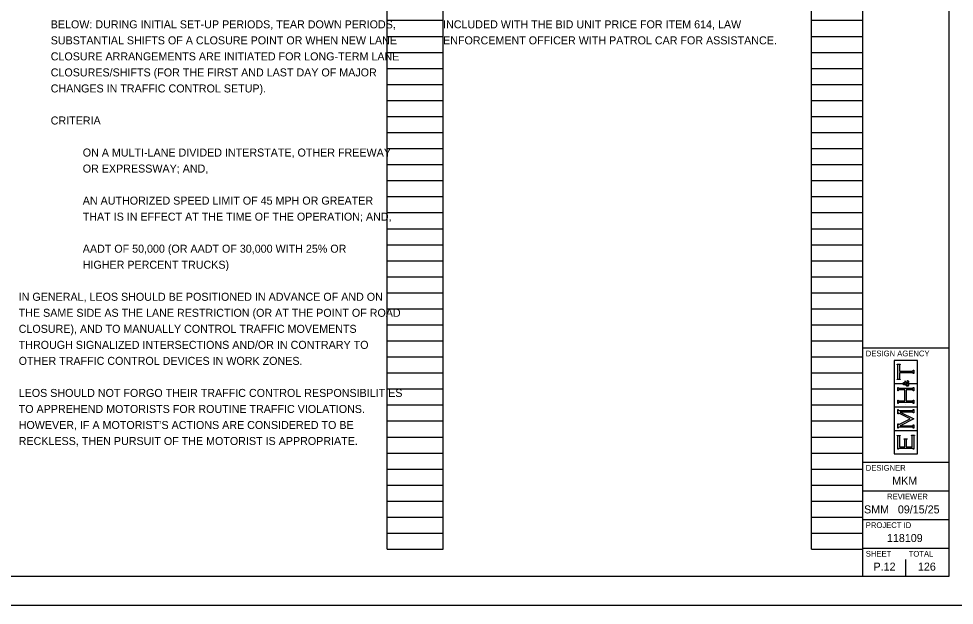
# Model space of a CAD drawing. Extents: x 0 to 50.5, y 0 to 22.
# Drawn here: x 17.24 to 33.6, y 0 to 10.25 of the extents above; entities that cross this region are included whole.
import ezdxf

# ---------------------------------------------------------------- set-up
doc = ezdxf.new("R2010")
doc.units = 0
for name, color, linetype in [('SH_Border', 7, 'Continuous'), ('SH_Cut_Line', 7, 'Continuous'), ('SH_Data', 7, 'Continuous'), ('SH_Text', 7, 'Continuous')]:
    doc.layers.add(name, color=color, linetype=linetype)

msp = doc.modelspace()

# ---------------------------------------------------------------- linework, layer by layer
at = {"layer": 'SH_Border'}
for p, q in [((32, 0.5), (32, 21.5)), ((32, 4.5), (33.5, 4.5)), ((32, 2.5), (33.5, 2.5)), ((32, 2), (33.5, 2)), ((32, 1.5), (33.5, 1.5)), ((32, 1), (33.5, 1))]:
    msp.add_line(p, q, dxfattribs=at)
msp.add_lwpolyline([(1.5, 21.5), (33.5, 21.5), (33.5, 0.5), (1.5, 0.5)], close=True, dxfattribs=at)
at = {"layer": 'SH_Cut_Line'}
msp.add_lwpolyline([(0, 0), (34, 0), (34, 22), (0, 22)], close=True, dxfattribs=at)
at = {"layer": 'SH_Data'}
for p, q in [((23.68, 0.98), (23.68, 21.14)), ((24.66, 0.98), (24.66, 21.14)), ((31.1, 0.98), (31.1, 21.14)), ((32, 0.98), (32, 21.14)), ((23.68, 10.22), (24.66, 10.22)), ((31.1, 10.22), (32, 10.22)), ((23.68, 9.94), (24.66, 9.94)), ((31.1, 9.94), (32, 9.94)), ((23.68, 9.66), (24.66, 9.66)), ((31.1, 9.66), (32, 9.66)), ((23.68, 9.38), (24.66, 9.38)), ((31.1, 9.38), (32, 9.38)), ((23.68, 9.1), (24.66, 9.1)), ((31.1, 9.1), (32, 9.1)), ((23.68, 8.82), (24.66, 8.82)), ((31.1, 8.82), (32, 8.82)), ((23.68, 8.54), (24.66, 8.54)), ((31.1, 8.54), (32, 8.54)), ((23.68, 8.26), (24.66, 8.26)), ((31.1, 8.26), (32, 8.26)), ((23.68, 7.98), (24.66, 7.98)), ((31.1, 7.98), (32, 7.98)), ((23.68, 7.7), (24.66, 7.7)), ((31.1, 7.7), (32, 7.7)), ((23.68, 7.42), (24.66, 7.42)), ((31.1, 7.42), (32, 7.42)), ((23.68, 7.14), (24.66, 7.14)), ((31.1, 7.14), (32, 7.14)), ((23.68, 6.86), (24.66, 6.86)), ((31.1, 6.86), (32, 6.86)), ((23.68, 6.58), (24.66, 6.58)), ((31.1, 6.58), (32, 6.58)), ((23.68, 6.3), (24.66, 6.3)), ((31.1, 6.3), (32, 6.3)), ((23.68, 6.02), (24.66, 6.02)), ((31.1, 6.02), (32, 6.02)), ((23.68, 5.74), (24.66, 5.74)), ((31.1, 5.74), (32, 5.74)), ((23.68, 5.46), (24.66, 5.46)), ((31.1, 5.46), (32, 5.46)), ((23.68, 5.18), (24.66, 5.18)), ((31.1, 5.18), (32, 5.18)), ((23.68, 4.9), (24.66, 4.9)), ((31.1, 4.9), (32, 4.9)), ((23.68, 4.62), (24.66, 4.62)), ((31.1, 4.62), (32, 4.62)), ((23.68, 4.34), (24.66, 4.34)), ((31.1, 4.34), (32, 4.34)), ((32.952, 4.279), (32.547, 4.279)), ((32.547, 4.279), (32.547, 3.875)), ((32.952, 3.875), (32.952, 4.279)), ((32.598, 4.204), (32.598, 4.211)), ((32.598, 4.211), (32.65, 4.211)), ((32.603, 4.203), (32.598, 4.204)), ((32.606, 4.201), (32.603, 4.203)), ((32.608, 4.199), (32.606, 4.201)), ((32.61, 4.196), (32.608, 4.199)), ((32.611, 4.192), (32.61, 4.196)), ((32.611, 4.187), (32.611, 4.192)), ((32.611, 3.968), (32.611, 4.187)), ((32.638, 4.196), (32.637, 4.192)), ((32.637, 4.192), (32.637, 4.187)), ((32.637, 4.187), (32.637, 4.093)), ((32.637, 4.093), (32.864, 4.093)), ((32.64, 4.199), (32.638, 4.196)), ((32.642, 4.201), (32.64, 4.199)), ((32.645, 4.203), (32.642, 4.201)), ((32.65, 4.204), (32.645, 4.203)), ((32.65, 4.211), (32.65, 4.204)), ((32.864, 4.093), (32.869, 4.093)), ((32.869, 4.093), (32.873, 4.094)), ((32.873, 4.094), (32.876, 4.096)), ((32.876, 4.096), (32.878, 4.097)), ((32.878, 4.097), (32.88, 4.101)), ((32.88, 4.101), (32.881, 4.106)), ((32.881, 4.106), (32.888, 4.106)), ((32.888, 4.106), (32.888, 4.048)), ((23.68, 4.06), (24.66, 4.06)), ((31.1, 4.06), (32, 4.06)), ((32.598, 3.95), (32.603, 3.951)), ((32.598, 3.944), (32.598, 3.95)), ((32.65, 3.944), (32.598, 3.944)), ((32.603, 3.951), (32.606, 3.953)), ((32.606, 3.953), (32.608, 3.955)), ((32.608, 3.955), (32.61, 3.958)), ((32.61, 3.958), (32.611, 3.962)), ((32.611, 3.962), (32.611, 3.968)), ((32.864, 4.061), (32.637, 4.061)), ((32.637, 4.061), (32.637, 3.968)), ((32.637, 3.968), (32.637, 3.962)), ((32.637, 3.962), (32.638, 3.958)), ((32.638, 3.958), (32.64, 3.955)), ((32.64, 3.955), (32.642, 3.953)), ((32.642, 3.953), (32.645, 3.951)), ((32.645, 3.951), (32.65, 3.95)), ((32.65, 3.95), (32.65, 3.944)), ((32.779, 3.923), (32.781, 3.926)), ((32.781, 3.926), (32.787, 3.924)), ((32.87, 4.061), (32.864, 4.061)), ((32.874, 4.06), (32.87, 4.061)), ((32.876, 4.059), (32.874, 4.06)), ((32.878, 4.057), (32.876, 4.059)), ((32.88, 4.053), (32.878, 4.057)), ((32.881, 4.048), (32.88, 4.053)), ((32.888, 4.048), (32.881, 4.048)), ((23.68, 3.78), (24.66, 3.78)), ((31.1, 3.78), (32, 3.78)), ((32.547, 3.875), (32.696, 3.875)), ((32.696, 3.869), (32.547, 3.869)), ((32.547, 3.869), (32.547, 3.465)), ((32.611, 3.749), (32.611, 3.807)), ((32.611, 3.807), (32.617, 3.807)), ((32.617, 3.807), (32.619, 3.802)), ((32.619, 3.802), (32.62, 3.798)), ((32.62, 3.798), (32.623, 3.797)), ((32.623, 3.797), (32.625, 3.795)), ((32.625, 3.795), (32.629, 3.794)), ((32.629, 3.762), (32.625, 3.761)), ((32.629, 3.794), (32.635, 3.794)), ((32.635, 3.762), (32.629, 3.762)), ((32.635, 3.794), (32.864, 3.794)), ((32.732, 3.762), (32.635, 3.762)), ((32.696, 3.875), (32.696, 3.869)), ((32.703, 3.879), (32.705, 3.883)), ((32.703, 3.873), (32.703, 3.879)), ((32.703, 3.868), (32.703, 3.873)), ((32.705, 3.863), (32.703, 3.868)), ((32.705, 3.883), (32.708, 3.887)), ((32.708, 3.858), (32.705, 3.863)), ((32.708, 3.887), (32.711, 3.89)), ((32.709, 3.879), (32.708, 3.876)), ((32.708, 3.876), (32.708, 3.873)), ((32.708, 3.873), (32.708, 3.869)), ((32.708, 3.869), (32.71, 3.866)), ((32.712, 3.853), (32.708, 3.858)), ((32.712, 3.881), (32.709, 3.879)), ((32.71, 3.866), (32.712, 3.864)), ((32.711, 3.89), (32.715, 3.892)), ((32.714, 3.883), (32.712, 3.881)), ((32.712, 3.864), (32.715, 3.862)), ((32.718, 3.85), (32.712, 3.853)), ((32.716, 3.884), (32.714, 3.883)), ((32.715, 3.892), (32.72, 3.892)), ((32.715, 3.862), (32.718, 3.861)), ((32.72, 3.884), (32.716, 3.884)), ((32.718, 3.861), (32.721, 3.861)), ((32.726, 3.85), (32.718, 3.85)), ((32.72, 3.892), (32.725, 3.892)), ((32.724, 3.884), (32.72, 3.884)), ((32.721, 3.861), (32.723, 3.861)), ((32.723, 3.861), (32.725, 3.862)), ((32.728, 3.882), (32.724, 3.884)), ((32.725, 3.892), (32.729, 3.89)), ((32.725, 3.862), (32.728, 3.862)), ((32.729, 3.85), (32.726, 3.85)), ((32.731, 3.88), (32.728, 3.882)), ((32.728, 3.862), (32.731, 3.863)), ((32.729, 3.89), (32.732, 3.887)), ((32.731, 3.85), (32.729, 3.85)), ((32.734, 3.877), (32.731, 3.88)), ((32.731, 3.863), (32.735, 3.865)), ((32.734, 3.851), (32.731, 3.85)), ((32.732, 3.887), (32.736, 3.883)), ((32.732, 3.572), (32.732, 3.762)), ((32.737, 3.872), (32.734, 3.877)), ((32.737, 3.852), (32.734, 3.851)), ((32.735, 3.865), (32.74, 3.867)), ((32.736, 3.883), (32.74, 3.878)), ((32.74, 3.867), (32.737, 3.872)), ((32.741, 3.853), (32.737, 3.852)), ((32.738, 3.893), (32.738, 3.922)), ((32.738, 3.922), (32.741, 3.922)), ((32.741, 3.893), (32.738, 3.893)), ((32.74, 3.878), (32.744, 3.869)), ((32.741, 3.922), (32.741, 3.918)), ((32.741, 3.918), (32.742, 3.915)), ((32.742, 3.896), (32.741, 3.895)), ((32.741, 3.895), (32.741, 3.893)), ((32.746, 3.855), (32.741, 3.853)), ((32.742, 3.915), (32.743, 3.913)), ((32.743, 3.897), (32.742, 3.896)), ((32.743, 3.913), (32.745, 3.911)), ((32.745, 3.899), (32.743, 3.897)), ((32.744, 3.869), (32.754, 3.875)), ((32.745, 3.911), (32.749, 3.908)), ((32.746, 3.899), (32.745, 3.899)), ((32.748, 3.899), (32.746, 3.899)), ((32.752, 3.844), (32.746, 3.855)), ((32.755, 3.899), (32.748, 3.899)), ((32.749, 3.908), (32.756, 3.904)), ((32.756, 3.86), (32.751, 3.857)), ((32.751, 3.857), (32.754, 3.852)), ((32.757, 3.837), (32.752, 3.844)), ((32.754, 3.875), (32.764, 3.881)), ((32.754, 3.852), (32.757, 3.848)), ((32.763, 3.895), (32.755, 3.899)), ((32.756, 3.904), (32.763, 3.9)), ((32.761, 3.863), (32.756, 3.86)), ((32.757, 3.848), (32.761, 3.845)), ((32.763, 3.833), (32.757, 3.837)), ((32.864, 3.762), (32.759, 3.762)), ((32.759, 3.762), (32.759, 3.572)), ((32.764, 3.865), (32.761, 3.863)), ((32.761, 3.845), (32.765, 3.843)), ((32.763, 3.9), (32.77, 3.896)), ((32.772, 3.887), (32.763, 3.895)), ((32.768, 3.829), (32.763, 3.833)), ((32.764, 3.881), (32.772, 3.887)), ((32.768, 3.867), (32.764, 3.865)), ((32.765, 3.843), (32.769, 3.841)), ((32.774, 3.872), (32.768, 3.867)), ((32.774, 3.827), (32.768, 3.829)), ((32.769, 3.841), (32.773, 3.841)), ((32.77, 3.896), (32.776, 3.891)), ((32.773, 3.841), (32.778, 3.841)), ((32.782, 3.878), (32.774, 3.872)), ((32.779, 3.827), (32.774, 3.827)), ((32.776, 3.891), (32.781, 3.895)), ((32.778, 3.841), (32.782, 3.843)), ((32.782, 3.922), (32.779, 3.923)), ((32.785, 3.827), (32.779, 3.827)), ((32.781, 3.895), (32.784, 3.898)), ((32.785, 3.921), (32.782, 3.922)), ((32.786, 3.873), (32.782, 3.878)), ((32.782, 3.843), (32.786, 3.846)), ((32.784, 3.898), (32.786, 3.901)), ((32.786, 3.919), (32.785, 3.921)), ((32.79, 3.829), (32.785, 3.827)), ((32.788, 3.917), (32.786, 3.919)), ((32.786, 3.901), (32.788, 3.904)), ((32.791, 3.886), (32.786, 3.881)), ((32.786, 3.881), (32.791, 3.876)), ((32.788, 3.869), (32.786, 3.873)), ((32.786, 3.846), (32.789, 3.849)), ((32.787, 3.924), (32.792, 3.921)), ((32.789, 3.914), (32.788, 3.917)), ((32.788, 3.904), (32.789, 3.908)), ((32.79, 3.867), (32.788, 3.869)), ((32.789, 3.911), (32.789, 3.914)), ((32.789, 3.908), (32.789, 3.911)), ((32.789, 3.849), (32.791, 3.853)), ((32.791, 3.864), (32.79, 3.867)), ((32.793, 3.834), (32.79, 3.829)), ((32.794, 3.89), (32.791, 3.886)), ((32.791, 3.876), (32.795, 3.87)), ((32.791, 3.861), (32.791, 3.864)), ((32.791, 3.859), (32.791, 3.861)), ((32.791, 3.853), (32.791, 3.859)), ((32.792, 3.921), (32.795, 3.918)), ((32.797, 3.838), (32.793, 3.834)), ((32.796, 3.894), (32.794, 3.89)), ((32.795, 3.918), (32.798, 3.914)), ((32.795, 3.87), (32.797, 3.866)), ((32.798, 3.897), (32.796, 3.894)), ((32.797, 3.866), (32.798, 3.861)), ((32.799, 3.844), (32.797, 3.838)), ((32.798, 3.914), (32.799, 3.91)), ((32.799, 3.901), (32.798, 3.897)), ((32.798, 3.861), (32.799, 3.857)), ((32.799, 3.91), (32.799, 3.905)), ((32.799, 3.905), (32.799, 3.901)), ((32.803, 3.869), (32.799, 3.875)), ((32.799, 3.875), (32.952, 3.875)), ((32.799, 3.857), (32.799, 3.852)), ((32.799, 3.852), (32.799, 3.844)), ((32.952, 3.869), (32.803, 3.869)), ((32.864, 3.794), (32.869, 3.794)), ((32.87, 3.762), (32.864, 3.762)), ((32.869, 3.794), (32.873, 3.795)), ((32.874, 3.761), (32.87, 3.762)), ((32.873, 3.795), (32.876, 3.797)), ((32.876, 3.797), (32.878, 3.798)), ((32.878, 3.798), (32.88, 3.802)), ((32.88, 3.802), (32.881, 3.807)), ((32.881, 3.807), (32.888, 3.807)), ((32.888, 3.807), (32.888, 3.749)), ((32.952, 3.465), (32.952, 3.869)), ((32.617, 3.749), (32.611, 3.749)), ((32.618, 3.754), (32.617, 3.749)), ((32.62, 3.758), (32.618, 3.754)), ((32.623, 3.76), (32.62, 3.758)), ((32.625, 3.761), (32.623, 3.76)), ((32.876, 3.76), (32.874, 3.761)), ((32.878, 3.758), (32.876, 3.76)), ((32.88, 3.754), (32.878, 3.758)), ((32.881, 3.749), (32.88, 3.754)), ((32.888, 3.749), (32.881, 3.749)), ((23.68, 3.5), (24.66, 3.5)), ((31.1, 3.5), (32, 3.5)), ((32.547, 3.465), (32.952, 3.465)), ((32.952, 3.459), (32.547, 3.459)), ((32.547, 3.459), (32.547, 3.055)), ((32.611, 3.527), (32.611, 3.585)), ((32.611, 3.585), (32.617, 3.585)), ((32.617, 3.527), (32.611, 3.527)), ((32.617, 3.585), (32.619, 3.58)), ((32.618, 3.532), (32.617, 3.527)), ((32.62, 3.536), (32.618, 3.532)), ((32.619, 3.58), (32.62, 3.576)), ((32.62, 3.576), (32.623, 3.574)), ((32.623, 3.537), (32.62, 3.536)), ((32.623, 3.574), (32.625, 3.573)), ((32.625, 3.539), (32.623, 3.537)), ((32.625, 3.573), (32.629, 3.572)), ((32.629, 3.54), (32.625, 3.539)), ((32.629, 3.572), (32.635, 3.572)), ((32.635, 3.54), (32.629, 3.54)), ((32.635, 3.572), (32.732, 3.572)), ((32.864, 3.54), (32.635, 3.54)), ((32.75, 3.5), (32.75, 3.5)), ((32.759, 3.572), (32.864, 3.572)), ((32.864, 3.572), (32.87, 3.572)), ((32.87, 3.54), (32.864, 3.54)), ((32.87, 3.572), (32.874, 3.573)), ((32.874, 3.539), (32.87, 3.54)), ((32.874, 3.573), (32.876, 3.574)), ((32.876, 3.538), (32.874, 3.539)), ((32.876, 3.574), (32.878, 3.576)), ((32.878, 3.536), (32.876, 3.538)), ((32.878, 3.576), (32.88, 3.58)), ((32.88, 3.532), (32.878, 3.536)), ((32.88, 3.58), (32.881, 3.585)), ((32.881, 3.527), (32.88, 3.532)), ((32.881, 3.585), (32.888, 3.585)), ((32.888, 3.527), (32.881, 3.527)), ((32.888, 3.585), (32.888, 3.527)), ((32.952, 3.055), (32.952, 3.459)), ((32.611, 3.345), (32.611, 3.418)), ((32.611, 3.418), (32.617, 3.418)), ((32.617, 3.345), (32.611, 3.345)), ((32.617, 3.418), (32.619, 3.412)), ((32.62, 3.352), (32.617, 3.345)), ((32.619, 3.412), (32.62, 3.409)), ((32.62, 3.409), (32.623, 3.407)), ((32.622, 3.355), (32.62, 3.352)), ((32.626, 3.355), (32.622, 3.355)), ((32.623, 3.407), (32.625, 3.405)), ((32.625, 3.405), (32.629, 3.405)), ((32.629, 3.355), (32.626, 3.355)), ((32.629, 3.405), (32.635, 3.405)), ((32.633, 3.353), (32.629, 3.355)), ((32.64, 3.35), (32.633, 3.353)), ((32.635, 3.405), (32.864, 3.405)), ((32.825, 3.257), (32.64, 3.35)), ((32.864, 3.373), (32.654, 3.373)), ((32.654, 3.373), (32.888, 3.255)), ((32.864, 3.405), (32.869, 3.405)), ((32.87, 3.373), (32.864, 3.373)), ((32.869, 3.405), (32.873, 3.405)), ((32.874, 3.372), (32.87, 3.373)), ((32.873, 3.405), (32.876, 3.407)), ((32.876, 3.37), (32.874, 3.372)), ((32.876, 3.407), (32.878, 3.409)), ((32.878, 3.369), (32.876, 3.37)), ((32.878, 3.409), (32.88, 3.412)), ((32.88, 3.365), (32.878, 3.369)), ((32.88, 3.412), (32.881, 3.418)), ((32.881, 3.36), (32.88, 3.365)), ((32.881, 3.418), (32.888, 3.418)), ((32.888, 3.36), (32.881, 3.36)), ((32.888, 3.418), (32.888, 3.36)), ((23.68, 3.22), (24.66, 3.22)), ((31.1, 3.22), (32, 3.22)), ((32.611, 3.096), (32.611, 3.168)), ((32.611, 3.168), (32.617, 3.168)), ((32.617, 3.168), (32.62, 3.162)), ((32.62, 3.162), (32.622, 3.158)), ((32.622, 3.158), (32.626, 3.158)), ((32.625, 3.109), (32.623, 3.107)), ((32.629, 3.109), (32.625, 3.109)), ((32.626, 3.158), (32.627, 3.158)), ((32.627, 3.158), (32.633, 3.161)), ((32.635, 3.109), (32.629, 3.109)), ((32.633, 3.161), (32.641, 3.165)), ((32.864, 3.109), (32.635, 3.109)), ((32.641, 3.165), (32.825, 3.257)), ((32.888, 3.255), (32.654, 3.138)), ((32.654, 3.138), (32.864, 3.138)), ((32.864, 3.138), (32.869, 3.138)), ((32.87, 3.109), (32.864, 3.109)), ((32.869, 3.138), (32.873, 3.139)), ((32.874, 3.109), (32.87, 3.109)), ((32.873, 3.139), (32.876, 3.141)), ((32.876, 3.107), (32.874, 3.109)), ((32.876, 3.141), (32.878, 3.143)), ((32.878, 3.143), (32.88, 3.146)), ((32.88, 3.146), (32.881, 3.151)), ((32.881, 3.151), (32.888, 3.151)), ((32.888, 3.151), (32.888, 3.096)), ((32.547, 3.055), (32.952, 3.055)), ((32.952, 3.049), (32.547, 3.049)), ((32.547, 3.049), (32.547, 2.645)), ((32.598, 2.962), (32.598, 2.969)), ((32.598, 2.969), (32.65, 2.969)), ((32.603, 2.961), (32.598, 2.962)), ((32.606, 2.959), (32.603, 2.961)), ((32.608, 2.957), (32.606, 2.959)), ((32.61, 2.955), (32.608, 2.957)), ((32.611, 2.951), (32.61, 2.955)), ((32.617, 3.096), (32.611, 3.096)), ((32.611, 2.945), (32.611, 2.951)), ((32.611, 2.725), (32.611, 2.945)), ((32.618, 3.102), (32.617, 3.096)), ((32.62, 3.105), (32.618, 3.102)), ((32.623, 3.107), (32.62, 3.105)), ((32.64, 2.957), (32.638, 2.955)), ((32.638, 2.955), (32.638, 2.951)), ((32.638, 2.951), (32.638, 2.945)), ((32.638, 2.945), (32.638, 2.77)), ((32.642, 2.959), (32.64, 2.957)), ((32.645, 2.961), (32.642, 2.959)), ((32.65, 2.962), (32.645, 2.961)), ((32.65, 2.969), (32.65, 2.962)), ((32.848, 2.965), (32.848, 2.972)), ((32.848, 2.972), (32.901, 2.972)), ((32.853, 2.964), (32.848, 2.965)), ((32.857, 2.962), (32.853, 2.964)), ((32.859, 2.96), (32.857, 2.962)), ((32.86, 2.958), (32.859, 2.96)), ((32.861, 2.953), (32.86, 2.958)), ((32.861, 2.948), (32.861, 2.953)), ((32.861, 2.77), (32.861, 2.948)), ((32.878, 3.105), (32.876, 3.107)), ((32.88, 3.102), (32.878, 3.105)), ((32.881, 3.096), (32.88, 3.102)), ((32.888, 3.096), (32.881, 3.096)), ((32.889, 2.957), (32.888, 2.953)), ((32.888, 2.953), (32.888, 2.948)), ((32.888, 2.948), (32.888, 2.725)), ((32.891, 2.96), (32.889, 2.957)), ((32.892, 2.962), (32.891, 2.96)), ((32.896, 2.964), (32.892, 2.962)), ((32.901, 2.965), (32.896, 2.964)), ((32.901, 2.972), (32.901, 2.965)), ((32.952, 2.645), (32.952, 3.049)), ((23.68, 2.94), (24.66, 2.94)), ((31.1, 2.94), (32, 2.94)), ((32.719, 2.902), (32.719, 2.908)), ((32.719, 2.908), (32.772, 2.908)), ((32.724, 2.901), (32.719, 2.902)), ((32.728, 2.899), (32.724, 2.901)), ((32.729, 2.896), (32.728, 2.899)), ((32.731, 2.894), (32.729, 2.896)), ((32.732, 2.89), (32.731, 2.894)), ((32.732, 2.884), (32.732, 2.89)), ((32.732, 2.77), (32.732, 2.884)), ((32.76, 2.894), (32.759, 2.89)), ((32.759, 2.89), (32.759, 2.884)), ((32.759, 2.884), (32.759, 2.77)), ((32.761, 2.896), (32.76, 2.894)), ((32.763, 2.899), (32.761, 2.896)), ((32.767, 2.901), (32.763, 2.899)), ((32.772, 2.902), (32.767, 2.901)), ((32.772, 2.908), (32.772, 2.902)), ((23.68, 2.66), (24.66, 2.66)), ((31.1, 2.66), (32, 2.66)), ((32.547, 2.645), (32.952, 2.645)), ((32.617, 2.725), (32.611, 2.725)), ((32.619, 2.73), (32.617, 2.725)), ((32.62, 2.734), (32.619, 2.73)), ((32.623, 2.735), (32.62, 2.734)), ((32.625, 2.737), (32.623, 2.735)), ((32.629, 2.738), (32.625, 2.737)), ((32.635, 2.738), (32.629, 2.738)), ((32.864, 2.738), (32.635, 2.738)), ((32.638, 2.77), (32.732, 2.77)), ((32.759, 2.77), (32.861, 2.77)), ((32.87, 2.738), (32.864, 2.738)), ((32.874, 2.737), (32.87, 2.738)), ((32.876, 2.735), (32.874, 2.737)), ((32.878, 2.734), (32.876, 2.735)), ((32.88, 2.73), (32.878, 2.734)), ((32.881, 2.725), (32.88, 2.73)), ((32.888, 2.725), (32.881, 2.725)), ((23.68, 2.38), (24.66, 2.38)), ((31.1, 2.38), (32, 2.38)), ((23.68, 2.1), (24.66, 2.1)), ((31.1, 2.1), (32, 2.1)), ((23.68, 1.82), (24.66, 1.82)), ((31.1, 1.82), (32, 1.82)), ((23.68, 1.54), (24.66, 1.54)), ((31.1, 1.54), (32, 1.54)), ((23.68, 1.26), (24.66, 1.26)), ((31.1, 1.26), (32, 1.26)), ((23.68, 0.98), (24.66, 0.98)), ((31.1, 0.98), (32, 0.98)), ((32.375, 0.675), (32.375, 0.675)), ((32.75, 0.5), (32.75, 0.8))]:
    msp.add_line(p, q, dxfattribs=at)

# ---------------------------------------------------------------- texts
for s, height, p in [('DESIGN AGENCY', 0.1, (32.05, 4.35)), ('DESIGNER', 0.1, (32.05, 2.35)), ('MKM', 0.14, (32.513, 2.105)), ('REVIEWER', 0.1, (32.422, 1.85)), ('SMM', 0.14, (32.02, 1.605)), ('09/15/25', 0.14, (32.611, 1.605)), ('PROJECT ID', 0.1, (32.05, 1.35)), ('118109', 0.14, (32.42, 1.105)), ('SHEET', 0.1, (32.05, 0.85)), ('TOTAL', 0.1, (32.8, 0.85)), ('P.12', 0.14, (32.185, 0.605)), ('126', 0.14, (32.962, 0.605))]:
    msp.add_text(s, height=height, dxfattribs=at).set_placement(p)
at = {"layer": 'SH_Text'}
for s, p in [('BELOW: DURING INITIAL SET-UP PERIODS, TEAR DOWN PERIODS, ', (17.8, 10.08)), ('INCLUDED WITH THE BID UNIT PRICE FOR ITEM 614, LAW ', (24.66, 10.08)), ('SUBSTANTIAL SHIFTS OF A CLOSURE POINT OR WHEN NEW LANE ', (17.8, 9.8)), ('ENFORCEMENT OFFICER WITH PATROL CAR FOR ASSISTANCE.', (24.66, 9.8)), ('CLOSURE ARRANGEMENTS ARE INITIATED FOR LONG-TERM LANE ', (17.8, 9.52)), ('CLOSURES/SHIFTS (FOR THE FIRST AND LAST DAY OF MAJOR ', (17.8, 9.24)), ('CHANGES IN TRAFFIC CONTROL SETUP). ', (17.8, 8.96)), ('CRITERIA', (17.8, 8.4)), ('ON A MULTI-LANE DIVIDED INTERSTATE, OTHER FREEWAY ', (18.36, 7.84)), ('OR EXPRESSWAY; AND,', (18.36, 7.56)), ('AN AUTHORIZED SPEED LIMIT OF 45 MPH OR GREATER ', (18.36, 7)), ('THAT IS IN EFFECT AT THE TIME OF THE OPERATION; AND,', (18.36, 6.72)), ('AADT OF 50,000 (OR AADT OF 30,000 WITH 25% OR ', (18.36, 6.16)), ('HIGHER PERCENT TRUCKS) ', (18.36, 5.88)), ('IN GENERAL, LEOS SHOULD BE POSITIONED IN ADVANCE OF AND ON ', (17.24, 5.32)), ('THE SAME SIDE AS THE LANE RESTRICTION (OR AT THE POINT OF ROAD ', (17.24, 5.04)), ('CLOSURE), AND TO MANUALLY CONTROL TRAFFIC MOVEMENTS ', (17.24, 4.76)), ('THROUGH SIGNALIZED INTERSECTIONS AND/OR IN CONTRARY TO ', (17.24, 4.48)), ('OTHER TRAFFIC CONTROL DEVICES IN WORK ZONES.', (17.24, 4.2)), ('LEOS SHOULD NOT FORGO THEIR TRAFFIC CONTROL RESPONSIBILITIES ', (17.24, 3.64)), ('TO APPREHEND MOTORISTS FOR ROUTINE TRAFFIC VIOLATIONS. ', (17.24, 3.36)), ('HOWEVER, IF A MOTORIST’S ACTIONS ARE CONSIDERED TO BE ', (17.24, 3.08)), ('RECKLESS, THEN PURSUIT OF THE MOTORIST IS APPROPRIATE.', (17.24, 2.8))]:
    msp.add_text(s, height=0.14, dxfattribs=at).set_placement(p)

doc.saveas('drawing.dxf')
